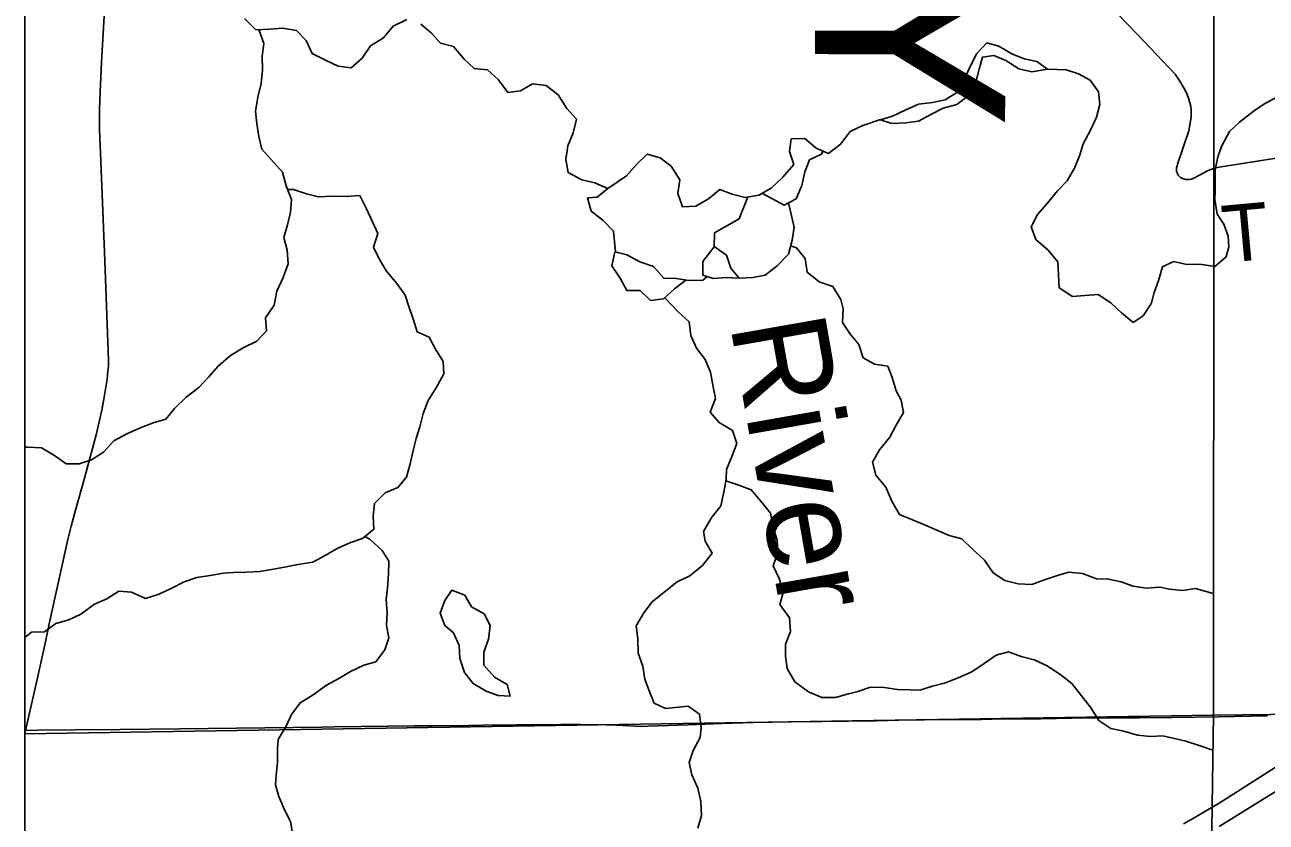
# Model space of a CAD drawing. Extents: x 0 to 34, y 0 to 22.
# Drawn here: x 2.1 to 3.335, y 15.737 to 16.53 of the extents above; entities that cross this region are included whole.
import ezdxf

# ---------------------------------------------------------------- set-up
doc = ezdxf.new("R2010")
doc.units = 0
for name, color, linetype in [('Default', 7, 'Continuous'), ('GM_X_County_Road', 7, 'Continuous'), ('GM_X_County_Text', 7, 'Continuous'), ('GM_X_Interstate_Route', 7, 'Continuous'), ('GM_X_Minor_Lake', 7, 'Continuous'), ('GM_X_Minor_River', 7, 'Continuous'), ('GM_X_Minor_River_Text', 7, 'Continuous'), ('GM_X_Township_Road', 7, 'Continuous'), ('GM_X_Township_Road_Text', 7, 'Continuous'), ('SH_Cut_Line', 7, 'Continuous'), ('SH_Data', 7, 'Continuous')]:
    doc.layers.add(name, color=color, linetype=linetype)

msp = doc.modelspace()

# ---------------------------------------------------------------- linework, layer by layer
at = {"layer": 'Default'}
for points in [[(3.2826, 20.9), (2.1, 20.9), (2.1, 15.8248), (3.2829, 15.8433), (3.2832, 16.3898), (3.2835, 17.0107), (3.2837, 17.3796), (3.2907, 18.4315), (3.2904, 19.1173), (3.2901, 19.68), (3.2888, 19.8918), (3.2845, 20.5998), (3.2843, 20.6124)], [(2.1, 15.8248), (2.1, 14.1), (3.2807, 14.1), (3.2808, 14.1155), (3.2822, 14.2781), (3.2841, 14.501), (3.2832, 14.8896), (3.2811, 15.7294), (3.2815, 15.7537), (3.2829, 15.8433)]]:
    msp.add_lwpolyline(points, close=True, dxfattribs=at)
for points in [[(8.1749, 20.9), (3.2826, 20.9), (3.2843, 20.6124), (3.2845, 20.5998), (3.2888, 19.8918), (3.2901, 19.68), (3.2904, 19.1173), (3.2907, 18.4315), (3.2837, 17.3796), (3.2835, 17.0107), (3.2832, 16.3898), (3.2829, 15.8433), (3.425, 15.8449), (3.4609, 15.8448), (3.6703, 15.8472), (4.3446, 15.8524), (4.6273, 15.8569)], [(4.6273, 15.8569), (4.3446, 15.8524), (3.6703, 15.8472), (3.4609, 15.8448), (3.425, 15.8449), (3.2829, 15.8433), (3.2815, 15.7537), (3.2811, 15.7294)]]:
    msp.add_lwpolyline(points, dxfattribs=at)
at = {"layer": 'GM_X_County_Road'}
for p, q in [((3.2874, 15.8416), (3.3366, 15.8426)), ((2.1, 15.825), (2.1008, 15.8279)), ((2.1, 15.8279), (2.1008, 15.8279))]:
    msp.add_line(p, q, dxfattribs=at)
for points in [[(2.1008, 15.8279), (2.1118, 15.8775), (2.1205, 15.9163), (2.1242, 15.934), (2.1428, 16.018), (2.1461, 16.0313), (2.1504, 16.0474), (2.1593, 16.0791), (2.1709, 16.1221), (2.174, 16.1353), (2.1766, 16.1469), (2.1786, 16.1578), (2.1807, 16.1696), (2.1818, 16.1775), (2.1827, 16.1855), (2.1831, 16.191), (2.1833, 16.1965), (2.1797, 16.2953), (2.1777, 16.3452), (2.1755, 16.3943), (2.1742, 16.426), (2.1744, 16.4461), (2.175, 16.4633), (2.1764, 16.4932), (2.1781, 16.5218), (2.1849, 16.6442)], [(2.1008, 15.8279), (2.113, 15.8282), (2.1501, 15.8285), (2.1944, 15.829), (2.2542, 15.8296), (2.3952, 15.8314), (2.4083, 15.8317), (2.4873, 15.8326), (2.5042, 15.8327), (2.5418, 15.8331), (2.5562, 15.8333), (2.5892, 15.8337), (2.6333, 15.8339), (2.6532, 15.8338), (2.6784, 15.8336), (2.6887, 15.8332), (2.7136, 15.8321), (2.7201, 15.8323), (2.74, 15.8328), (2.7599, 15.8336), (2.7688, 15.834), (2.7935, 15.8349), (2.8247, 15.8358), (2.8626, 15.8365), (2.8932, 15.8369), (2.9192, 15.8372), (2.9475, 15.8377), (2.9698, 15.8381), (2.9953, 15.8385), (3.0402, 15.839), (3.0519, 15.839), (3.0624, 15.8394), (3.0919, 15.8395), (3.1111, 15.8397), (3.1423, 15.8401), (3.179, 15.8405), (3.2091, 15.8406), (3.2414, 15.841), (3.2874, 15.8416)]]:
    msp.add_lwpolyline(points, dxfattribs=at)
at = {"layer": 'GM_X_Interstate_Route'}
for points in [[(3.2883, 15.7557), (3.3742, 15.8104), (3.4252, 15.8444), (3.4615, 15.8686), (3.5692, 15.9376), (3.6732, 16.0058), (3.7824, 16.0765), (3.9368, 16.1769), (3.9615, 16.1929), (3.983, 16.207), (4.0953, 16.2802), (4.2473, 16.3787), (4.4606, 16.518), (4.4783, 16.5295), (4.5617, 16.5838), (4.8848, 16.7932), (4.8864, 16.7942)], [(3.2884, 15.7323), (3.3713, 15.7839), (3.3812, 15.7905)], [(3.2528, 15.7349), (3.2659, 15.7423), (3.2748, 15.7477), (3.2883, 15.7557)]]:
    msp.add_lwpolyline(points, dxfattribs=at)
at = {"layer": 'GM_X_Minor_Lake'}
msp.add_line((3.1175, 16.4863), (3.1069, 16.4938), dxfattribs=at)
for points in [[(3.1069, 16.4938), (3.0944, 16.4965), (3.0822, 16.5014), (3.0692, 16.509), (3.0574, 16.5124), (3.0472, 16.5018), (3.0407, 16.4888), (3.0346, 16.4759), (3.0282, 16.4633), (3.0157, 16.4557), (3.0031, 16.453), (2.9894, 16.4515), (2.9765, 16.4458), (2.9635, 16.4393), (2.9514, 16.4358), (2.9628, 16.4321), (2.9765, 16.4328), (2.9894, 16.4344), (3.0016, 16.4412), (3.0138, 16.4473), (3.0275, 16.4512), (3.04, 16.4607), (3.0464, 16.4732), (3.0495, 16.4862), (3.0529, 16.4983), (3.0643, 16.4999), (3.0761, 16.4949), (3.089, 16.4866), (3.102, 16.4836), (3.1175, 16.4863)], [(3.1176, 16.4863), (3.1069, 16.4938), (3.0944, 16.4965), (3.0822, 16.5014), (3.0692, 16.509), (3.0574, 16.5124), (3.0472, 16.5018), (3.0407, 16.4888), (3.0346, 16.4759), (3.0282, 16.4633), (3.0157, 16.4557), (3.0031, 16.453), (2.9894, 16.4515), (2.9765, 16.4458), (2.9635, 16.4393), (2.9514, 16.4358), (2.9628, 16.4321), (2.9765, 16.4328), (2.9894, 16.4344), (3.0016, 16.4412), (3.0138, 16.4473), (3.0275, 16.4512), (3.04, 16.4607), (3.0464, 16.4732), (3.0495, 16.4862), (3.0529, 16.4983), (3.0643, 16.4999), (3.0761, 16.4949), (3.089, 16.4866), (3.102, 16.4836), (3.1175, 16.4863)], [(2.5798, 15.8738), (2.5675, 15.8809), (2.5568, 15.8931), (2.5568, 15.906), (2.5614, 15.9189), (2.5629, 15.9326), (2.5571, 15.944), (2.5446, 15.9512), (2.5377, 15.9626), (2.5248, 15.9675), (2.5179, 15.9573), (2.5134, 15.9447), (2.518, 15.9326)], [(2.5801, 15.8737), (2.5675, 15.8809), (2.5568, 15.8931), (2.5568, 15.906), (2.5614, 15.9189), (2.5629, 15.9326), (2.5571, 15.944), (2.5446, 15.9512), (2.5377, 15.9626), (2.5248, 15.9675), (2.5179, 15.9573), (2.5134, 15.9447), (2.518, 15.9326)], [(2.518, 15.9326), (2.5264, 15.9253), (2.5321, 15.9124), (2.5329, 15.8995), (2.5374, 15.8858), (2.5462, 15.8748), (2.5592, 15.8672), (2.571, 15.8627), (2.5831, 15.8623), (2.5798, 15.8738)], [(2.518, 15.9326), (2.5264, 15.9253), (2.5321, 15.9124), (2.5329, 15.8995), (2.5374, 15.8858), (2.5462, 15.8748), (2.5592, 15.8672), (2.571, 15.8627), (2.5831, 15.8623), (2.5798, 15.8737)]]:
    msp.add_lwpolyline(points, dxfattribs=at)
at = {"layer": 'GM_X_Minor_River'}
for points in [[(2.3185, 16.5366), (2.3299, 16.5252), (2.3436, 16.5259), (2.3565, 16.5271), (2.3702, 16.5248), (2.3798, 16.5146), (2.3859, 16.5017), (2.3992, 16.4952), (2.4118, 16.4891), (2.4247, 16.4876), (2.4357, 16.4972), (2.4441, 16.5093), (2.457, 16.5173), (2.4665, 16.5291), (2.4802, 16.5356)], [(2.4939, 16.5311), (2.5042, 16.5223), (2.5137, 16.5121), (2.5266, 16.5087), (2.5373, 16.4961), (2.5472, 16.487), (2.5605, 16.4855), (2.5712, 16.4757), (2.5807, 16.4631), (2.5933, 16.4647), (2.6051, 16.4715), (2.6188, 16.47), (2.6306, 16.4605), (2.6394, 16.4472), (2.6489, 16.4366), (2.6455, 16.4229), (2.6402, 16.41), (2.6383, 16.3963), (2.6406, 16.3833), (2.6543, 16.3761), (2.6672, 16.3731), (2.6802, 16.3674), (2.6695, 16.3587), (2.66, 16.3583), (2.6635, 16.345), (2.6753, 16.3358), (2.6856, 16.3248), (2.6876, 16.3043)], [(2.3333, 16.5254), (2.3333, 16.5248), (2.3379, 16.5119), (2.336, 16.4993), (2.3364, 16.4856), (2.3353, 16.4719), (2.3319, 16.4582), (2.3296, 16.4445), (2.3308, 16.432), (2.3327, 16.4191), (2.3358, 16.4065), (2.3564, 16.3837), (2.3602, 16.37), (2.3655, 16.3564), (2.3644, 16.3434), (2.3614, 16.3313), (2.3576, 16.3187), (2.361, 16.3062), (2.3622, 16.2925), (2.3569, 16.2788), (2.3508, 16.2651), (2.3482, 16.2514), (2.3394, 16.2388), (2.3406, 16.2259), (2.3307, 16.2156), (2.3174, 16.2087), (2.3045, 16.2011), (2.2923, 16.1905), (2.2828, 16.1798), (2.273, 16.1695), (2.2604, 16.1596), (2.249, 16.1486), (2.2403, 16.1379), (2.2277, 16.1341), (2.214, 16.1288), (2.2015, 16.1234), (2.1886, 16.1162), (2.1783, 16.1051), (2.1665, 16.0975), (2.154, 16.0933), (2.141, 16.0933), (2.1296, 16.1016), (2.1167, 16.1092), (2.103, 16.11), (2.1, 16.11)], [(3.2841, 16.2899), (3.2693, 16.2921), (3.2564, 16.2917), (3.243, 16.2947), (3.232, 16.2894), (3.2282, 16.2757), (3.2233, 16.2628), (3.221, 16.2533), (3.2127, 16.2407), (3.2028, 16.2342), (3.1914, 16.2437), (3.1807, 16.2536), (3.1681, 16.2619), (3.1548, 16.2608), (3.1426, 16.26), (3.1293, 16.2687), (3.1278, 16.2946), (3.1182, 16.306), (3.106, 16.3166), (3.1014, 16.3292), (3.1075, 16.3414), (3.1174, 16.3524), (3.1276, 16.365), (3.1371, 16.3752), (3.1444, 16.3878), (3.1493, 16.4), (3.1531, 16.4118), (3.1603, 16.4255), (3.1664, 16.4384), (3.1698, 16.451), (3.1682, 16.4635), (3.1602, 16.4753), (3.1484, 16.4817), (3.1362, 16.4855), (3.1175, 16.4863)], [(3.3466, 16.4588), (3.333, 16.4515), (3.3224, 16.4442), (3.3085, 16.4334), (3.2987, 16.4242), (3.2909, 16.4093), (3.2871, 16.399), (3.2844, 16.386), (3.2843, 16.3648), (3.2842, 16.3565), (3.2865, 16.342)], [(2.9516, 16.436), (2.9339, 16.4301), (2.9213, 16.424), (2.9118, 16.4114), (2.8997, 16.4023), (2.8875, 16.4076), (2.8761, 16.4171), (2.8627, 16.4167), (2.8609, 16.4042), (2.8651, 16.3912), (2.8544, 16.3787), (2.8427, 16.3676), (2.8305, 16.3608), (2.8168, 16.3585), (2.8039, 16.3619), (2.7917, 16.3664), (2.7803, 16.3573), (2.7677, 16.35), (2.7544, 16.3493), (2.7498, 16.3626), (2.7517, 16.3759), (2.7433, 16.3896), (2.7323, 16.3979), (2.7193, 16.4017), (2.7091, 16.3918), (2.6988, 16.38), (2.6801, 16.3674)], [(2.8942, 16.4047), (2.8928, 16.4015), (2.8807, 16.3958), (2.8761, 16.384), (2.8731, 16.3703), (2.8674, 16.357), (2.8556, 16.3509), (2.8339, 16.3626)], [(2.3616, 16.3664), (2.3674, 16.3663), (2.3804, 16.3621), (2.3922, 16.3591), (2.4059, 16.3598), (2.4196, 16.3595), (2.4333, 16.3606), (2.4397, 16.3477), (2.4458, 16.3344), (2.4512, 16.3226), (2.447, 16.3089), (2.4528, 16.2968), (2.46, 16.285), (2.4703, 16.2728), (2.4783, 16.2611), (2.4825, 16.2489), (2.4867, 16.2367), (2.4905, 16.2246), (2.5023, 16.2196), (2.5088, 16.2075), (2.5164, 16.1953), (2.5168, 16.1828), (2.5096, 16.1698), (2.5013, 16.1565), (2.4964, 16.1436), (2.4929, 16.1303), (2.4895, 16.1185), (2.4861, 16.1052), (2.4831, 16.0922), (2.4797, 16.08), (2.4713, 16.0698), (2.4584, 16.0644), (2.4478, 16.0538), (2.4467, 16.0412), (2.4474, 16.0283), (2.436, 16.0191), (2.4235, 16.0149), (2.4109, 16.0092), (2.3988, 16.002), (2.3866, 15.9955), (2.3737, 15.9936), (2.36, 15.9909), (2.3474, 15.9886), (2.3337, 15.9863), (2.3204, 15.9855), (2.3075, 15.9851), (2.2976, 15.9844), (2.2843, 15.9824), (2.2713, 15.9801), (2.2584, 15.9759), (2.2451, 15.9691), (2.2326, 15.9634), (2.22, 15.9592), (2.2063, 15.9656), (2.1934, 15.9667), (2.1816, 15.9591), (2.1694, 15.9538), (2.1557, 15.9439), (2.1439, 15.9382), (2.131, 15.9343), (2.1196, 15.9263), (2.1067, 15.9259), (2.1, 15.9206)], [(2.8598, 16.353), (2.8655, 16.3289), (2.8637, 16.3159), (2.8599, 16.3022), (2.8485, 16.2904), (2.8367, 16.2813), (2.8245, 16.279), (2.8108, 16.2782), (2.8024, 16.2881), (2.7982, 16.301), (2.786, 16.3098), (2.7864, 16.3234), (2.8107, 16.3372), (2.8195, 16.359)], [(3.2865, 16.342), (3.2931, 16.3318), (3.2973, 16.3201), (3.2982, 16.3094), (3.2953, 16.2995), (3.2841, 16.2899)], [(2.8099, 16.2783), (2.7979, 16.279), (2.785, 16.2778), (2.7747, 16.2812), (2.7747, 16.2949), (2.786, 16.3094)], [(2.8619, 16.3105), (2.8679, 16.3083), (2.8766, 16.2977), (2.8785, 16.284), (2.8904, 16.2745), (2.9041, 16.27), (2.9121, 16.2571), (2.9144, 16.2476), (2.9136, 16.2339), (2.9216, 16.2221), (2.93, 16.2122), (2.9342, 16.1989), (2.9456, 16.1925), (2.9586, 16.1906), (2.9632, 16.1792), (2.967, 16.1662), (2.972, 16.1567), (2.9743, 16.1446), (2.967, 16.132), (2.9606, 16.1198), (2.9503, 16.1073), (2.9435, 16.0951), (2.9469, 16.0822), (2.9569, 16.07), (2.9626, 16.0563), (2.9702, 16.043), (2.9832, 16.0377), (2.9953, 16.0328), (3.0197, 16.0222), (3.0323, 16.0188), (3.0433, 16.0081), (3.0548, 15.9975), (3.0635, 15.985), (3.0753, 15.9774), (3.0883, 15.974), (3.102, 15.9732), (3.1145, 15.9778), (3.1274, 15.9824), (3.1389, 15.9854), (3.1526, 15.9843), (3.1663, 15.979), (3.1784, 15.9787), (3.191, 15.976), (3.2028, 15.9715), (3.2157, 15.9696), (3.2294, 15.9707), (3.239, 15.9688), (3.2519, 15.9673), (3.2648, 15.9693), (3.2823, 15.9644)], [(2.7789, 16.2798), (2.7747, 16.2763), (2.761, 16.2759), (2.748, 16.2778), (2.7359, 16.2781), (2.7256, 16.2899), (2.7119, 16.2944), (2.6989, 16.3013), (2.6871, 16.3043), (2.6841, 16.2906), (2.6925, 16.2781), (2.699, 16.2659), (2.7123, 16.2659), (2.7226, 16.256), (2.7355, 16.2576), (2.7465, 16.2675), (2.7578, 16.2762)], [(2.737, 16.2585), (2.75, 16.2447), (2.761, 16.2348), (2.7626, 16.2211), (2.7683, 16.2086), (2.7771, 16.1972), (2.7824, 16.1846), (2.7847, 16.1717), (2.7874, 16.1584), (2.7821, 16.1447), (2.7909, 16.1344), (2.8042, 16.1265), (2.8084, 16.1136), (2.8035, 16.1006), (2.7982, 16.0877), (2.7978, 16.0782), (2.7955, 16.0652), (2.7925, 16.0515), (2.783, 16.0394), (2.7754, 16.026), (2.777, 16.0165), (2.7838, 16.0044), (2.7743, 15.9922), (2.7618, 15.9819), (2.7492, 15.9758), (2.7378, 15.9671), (2.7242, 15.956), (2.7158, 15.945), (2.7082, 15.932), (2.7101, 15.9191), (2.7102, 15.905), (2.7151, 15.8921), (2.717, 15.8792), (2.7212, 15.8674), (2.7262, 15.8552), (2.7376, 15.8499), (2.7506, 15.8511), (2.7601, 15.8522), (2.7715, 15.8443), (2.773, 15.831), (2.7719, 15.8211), (2.7651, 15.8081), (2.7609, 15.796), (2.7636, 15.7838), (2.7697, 15.7705), (2.7728, 15.7572), (2.7732, 15.7435), (2.7698, 15.7306)], [(2.7975, 16.0763), (2.7975, 16.0763), (2.8104, 16.0721), (2.8229, 16.0676), (2.8325, 16.0562), (2.842, 16.0444), (2.8443, 16.0315), (2.8485, 16.0174), (2.8493, 16.0052), (2.8447, 15.9919), (2.8505, 15.9794), (2.855, 15.9664), (2.8513, 15.9535), (2.8608, 15.9402), (2.8619, 15.9265), (2.857, 15.914), (2.857, 15.9018), (2.8586, 15.8896), (2.8662, 15.8763), (2.8799, 15.8665), (2.8929, 15.8608), (2.9066, 15.8608), (2.9195, 15.8646), (2.929, 15.8669), (2.9416, 15.8711), (2.9552, 15.8708), (2.9682, 15.8689), (2.9811, 15.8685), (2.9906, 15.8681), (3.0032, 15.872), (3.0161, 15.8754), (3.0287, 15.8804), (3.0424, 15.8865), (3.0545, 15.8945), (3.0667, 15.9028), (3.0789, 15.9063), (3.0914, 15.9017), (3.1044, 15.8983), (3.1165, 15.8926), (3.1299, 15.8839), (3.1417, 15.8748), (3.1516, 15.8626), (3.1611, 15.8501), (3.1688, 15.8379), (3.1806, 15.83), (3.1935, 15.8273), (3.2072, 15.8232), (3.2201, 15.822), (3.2323, 15.8228), (3.2453, 15.8198), (3.2552, 15.8175), (3.2677, 15.8134), (3.282, 15.8083)], [(2.4383, 16.0209), (2.4433, 16.0184), (2.4555, 16.007), (2.4623, 15.9964), (2.462, 15.9834), (2.4608, 15.9701), (2.4597, 15.9583), (2.4605, 15.945), (2.4598, 15.9329), (2.4621, 15.9203), (2.4583, 15.9081), (2.4492, 15.8963), (2.4374, 15.8929), (2.4241, 15.8868), (2.4123, 15.8796), (2.4001, 15.8731), (2.3868, 15.8636), (2.3739, 15.8555), (2.3655, 15.8438), (2.3598, 15.8316), (2.3522, 15.819), (2.3515, 15.8095), (2.3515, 15.7966), (2.35, 15.7833), (2.3493, 15.7738), (2.3527, 15.7624), (2.3584, 15.7491), (2.3642, 15.7373), (2.3661, 15.7278)]]:
    msp.add_lwpolyline(points, dxfattribs=at)
at = {"layer": 'GM_X_Township_Road'}
for points in [[(3.2904, 16.3891), (3.2843, 16.3879), (3.2817, 16.387), (3.2768, 16.3849), (3.269, 16.3806), (3.2627, 16.3774), (3.2605, 16.3766), (3.2586, 16.3763), (3.2548, 16.3765), (3.2529, 16.3771), (3.2512, 16.3778), (3.2499, 16.3785), (3.2489, 16.3793), (3.2479, 16.3804), (3.2472, 16.3813), (3.2465, 16.383), (3.2461, 16.3847), (3.246, 16.3863), (3.2461, 16.3879), (3.2465, 16.3899), (3.2469, 16.3916), (3.2581, 16.4247), (3.2589, 16.4289), (3.2599, 16.4344), (3.2605, 16.4388), (3.2607, 16.4427), (3.2606, 16.4455), (3.2602, 16.449), (3.2594, 16.4528), (3.2583, 16.4563), (3.2561, 16.462), (3.2536, 16.467), (3.2492, 16.4744), (3.2445, 16.4813), (3.2074, 16.5203), (3.1862, 16.5424)], [(3.2904, 16.3891), (3.3494, 16.3984), (3.399, 16.4052), (3.4626, 16.4122), (3.5271, 16.4197), (3.5869, 16.4272), (3.667, 16.4371), (3.6855, 16.4388)]]:
    msp.add_lwpolyline(points, dxfattribs=at)
at = {"layer": 'SH_Cut_Line'}
for points in [[(3.2826, 20.9), (2.1, 20.9), (2.1, 14.1), (3.2807, 14.1), (3.2808, 14.1155), (3.2822, 14.2781), (3.2841, 14.501), (3.2832, 14.8896), (3.2811, 15.7294), (3.2815, 15.7537), (3.2829, 15.8433), (3.2832, 16.3898), (3.2835, 17.0107), (3.2837, 17.3796), (3.2907, 18.4315), (3.2904, 19.1173), (3.2901, 19.68), (3.2888, 19.8918), (3.2845, 20.5998), (3.2843, 20.6124)], [(3.2807, 14.1), (8.9, 14.1), (8.9, 20.9), (3.2826, 20.9), (3.2843, 20.6124), (3.2845, 20.5998), (3.2888, 19.8918), (3.2901, 19.68), (3.2904, 19.1173), (3.2907, 18.4315), (3.2837, 17.3796), (3.2835, 17.0107), (3.2832, 16.3898), (3.2829, 15.8433), (3.2815, 15.7537), (3.2811, 15.7294), (3.2832, 14.8896), (3.2841, 14.501), (3.2822, 14.2781), (3.2808, 14.1155)]]:
    msp.add_lwpolyline(points, close=True, dxfattribs=at)
at = {"layer": 'SH_Data'}
msp.add_line((2.1, 20.9), (2.1, 14.1), dxfattribs=at)

# ---------------------------------------------------------------- texts
at = {"layer": 'GM_X_County_Text'}
msp.add_text('MEDINA COUNTY', height=0.189394, rotation=269.7794, dxfattribs=at).set_placement((2.8942, 18.553))
at = {"layer": 'GM_X_Minor_River_Text'}
msp.add_text('River', height=0.09474, rotation=279.9822, dxfattribs=at).set_placement((2.8016, 16.2322))
at = {"layer": 'GM_X_Township_Road_Text'}
msp.add_text('T', height=0.0568, rotation=5.197, dxfattribs=at).set_placement((3.2939, 16.2934))

doc.saveas('drawing.dxf')
